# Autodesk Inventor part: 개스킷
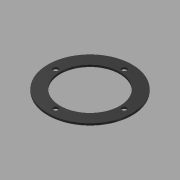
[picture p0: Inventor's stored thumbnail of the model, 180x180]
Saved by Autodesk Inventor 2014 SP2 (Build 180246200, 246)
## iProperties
Created: 2018-06
Part Number: 개스킷
Material: 고무
Document SubType Name: Modeling
Designer: G4400
Density: 0.93 g/cm^3
Appearance: 고무 - 검은색 - 버전 1.1
Mass: 2.24056 g
Surface Area: 38.1075 cm^2
Volume: 2.40921 cm^3
Author: G4400
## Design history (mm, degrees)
sketch "스케치1"
  geometry: C1 r 32.5 at (0, 0); C2 r 23 at (0, 0); 1 further point
  constraints: 2 centre point, 2 coincident
  dimensions: "d0" = 65 diameter of C1; "d1" = 46 diameter of C2
extrude "돌출1" new body sketch "스케치1" distance "d2" = 1.5; taper "d3" = 0 deg
sketch "스케치2" dims "d5" = 26.5
  geometry: C1 r 23 at (0, 0) reference; C2 r 32.5 at (0, 0) reference; 5 further points
  constraints: 2 vertical alignment, 1 coincident, 7 other
  dimensions: "d9" = 360 deg dimension on C1.centre point (0, 26.5) (derived)
hole "구멍1" sketch "스케치2" at (0, 26.5), (-26.5, 0), (0, -26.5), (26.5, 0) diameter "d11" = 4; stored, may be unused: countersink angle "d15" = 90 deg, drill point angle "d17" = 118 deg; dims "d12" = 6, "d13" = 4, "d14" = 2, "d16" = 8
node "솔리드1"
